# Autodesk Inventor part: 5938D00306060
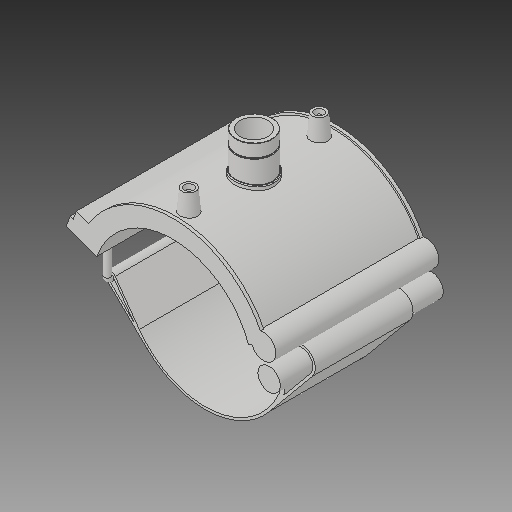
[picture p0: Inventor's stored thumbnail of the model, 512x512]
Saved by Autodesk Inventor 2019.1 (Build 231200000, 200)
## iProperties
Created: 2017-07
Part Number: 5938D00306060
Material: Generic
Description: PLASSON TRANSITION SADDLE 6''DIPS x 1"NPT
Document SubType Name: Modeling
Designer: KIM
Density: 1 g/cm^3
Appearance: Default
Author: KIM
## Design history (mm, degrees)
derived "5938D.ipt"
feature "Solid1::5938D.ipt"
tag "TaggingFeature1"
body "Solid1"
other parameters: "d_" = 174.5, "B_" = 176.784, "H_" = 41.91, "L_" = 176.022, "d_t" = 6, "G_" = 30.291, "d148" = 2.6175, "d160" = 2.6175, "d169" = 2.6175, "d192" = 6.98, "d0" = 174.5, "d1" = 209.4, "d2" = 441.96, "d3" = 43.625, "d4" = 176.022, "d5" = 0, "d40" = 108.888, "d41" = 42.4074, "d43" = 0, "d45" = 0, "d47" = 146.61, "d48" = 39.3783, "d50" = 0, "d78" = 126.7, "d79" = 15, "d80" = 70.4088, "d82" = 5 deg, "d84" = 4, "d85" = 14, "d86" = 0, "d87" = 3, "d88" = 0, "d96" = 213.588, "d97" = 3.52044, "d98" = 0, "d102" = 0.90873, "d103" = 30.291, "d104" = 25.146, "d105" = 0, "d106" = 24.2328, "d108" = 0, "d109" = -13.97, "d111" = 0.5, "d112" = 0.5, "d113" = 0, "d114" = 0.5, "d117" = 0.30291, "d120" = 140 deg, "d121" = 24.228, "d122" = 20 deg, "d123" = 837.6, "d124" = 125.64, "d126" = 0, "d143" = 179.735, "d145" = 26.84615, "d149" = 2.6175, "d150" = 29.53077, "d153" = 176.022, "d154" = 0, "d156" = 104.7, "d157" = 160 deg, "d159" = 6.98, "d161" = 2.6175, "d162" = 105.6132, "d163" = 0, "d164" = 87.25, "d167" = 17.45, "d168" = 102.14634, "d170" = 2.6175, "d172" = 0, "d173" = 1, "d175" = 87.25, "d176" = 20 deg, "d177" = 12.215, "d178" = 34.9, "d180" = 0, "d183" = 13.96, "d184" = 9.772, "d185" = 57.20715, "d186" = 57.20715, "d187" = 104.7, "d188" = 10.47, "d189" = 12.215, "d190" = 0, "d191" = 125.64, "d193" = 6.98, "d194" = 3.57725, "d195" = 90 deg, "d197" = 0, "d199" = 0
